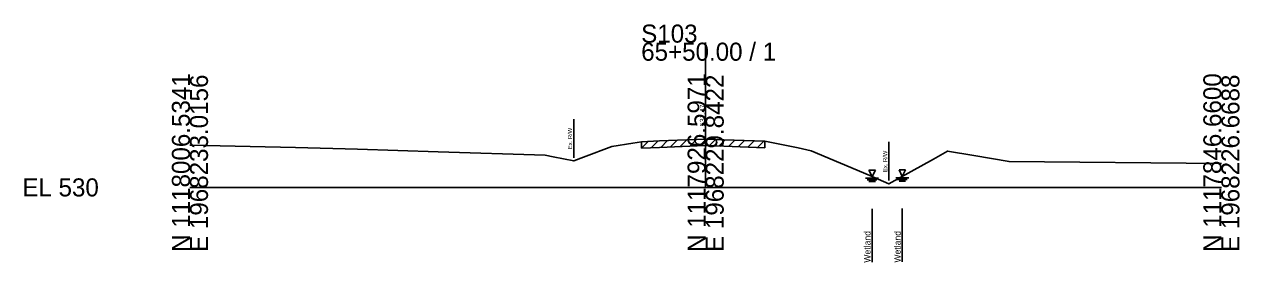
# Model space of a CAD drawing. Extents: x -26 to 163, y -10 to 24018.
# Drawn here: x -25.7 to 162.8, y 13488.3 to 13525.3 of the extents above; entities that cross this region are included whole.
import ezdxf

# ---------------------------------------------------------------- set-up
doc = ezdxf.new("R2010")
doc.units = 0
for name, color, linetype in [('RD_GPK_XS_Cell', 7, 'Continuous'), ('RD_XS_ExGround', 7, 'Continuous'), ('RD_XS_ExPaveRet', 7, 'Continuous'), ('RD_XS_ExRW', 7, 'Continuous'), ('RD_XS_EXWetland', 7, 'Continuous'), ('RD_XS_TX_Elev_EX', 7, 'Continuous')]:
    doc.layers.add(name, color=color, linetype=linetype)

msp = doc.modelspace()

# ---------------------------------------------------------------- linework, layer by layer
at = {"layer": 'RD_GPK_XS_Cell'}
for p, q in [((80, 13500), (80, 13522.43)), ((0, 13500), (80, 13500)), ((80, 13500), (160, 13500))]:
    msp.add_line(p, q, dxfattribs=at)
at = {"layer": 'RD_XS_ExGround'}
msp.add_lwpolyline([(0, 13506.55), (16.38, 13506.19), (26.01, 13505.93), (38.53, 13505.52), (55.09, 13504.98), (56.34, 13504.75), (59.53, 13504.1), (61.07, 13504.69), (65.47, 13506.33), (68.7, 13506.86), (70.04, 13507.08), (72.86, 13507.2), (79.89, 13507.48), (82.8, 13507.37), (89.2, 13507.15), (94.37, 13506.12), (96.38, 13505.69), (105.48, 13501.84), (108.41, 13500.55), (115.34, 13504.4), (117.53, 13505.64), (121.62, 13504.94), (127.08, 13504.01), (160, 13503.68)], dxfattribs=at)
at = {"layer": 'RD_XS_ExPaveRet'}
for p, q in [((70.04, 13506.08), (71.09, 13507.12)), ((70.04, 13506.08), (70.04, 13507.08)), ((71.54, 13506.14), (72.59, 13507.19)), ((73.04, 13506.21), (74.09, 13507.25)), ((74.54, 13506.27), (75.59, 13507.31)), ((76.04, 13506.32), (77.09, 13507.37)), ((77.54, 13506.38), (78.59, 13507.42)), ((79.04, 13506.44), (80.07, 13507.47)), ((80.54, 13506.45), (81.51, 13507.42)), ((82.04, 13506.4), (83.01, 13507.36)), ((83.54, 13506.34), (84.51, 13507.31)), ((85.04, 13506.29), (86.01, 13507.26)), ((86.54, 13506.24), (87.51, 13507.21)), ((88.04, 13506.19), (89.01, 13507.15)), ((89.2, 13507.15), (89.2, 13506.15)), ((70.04, 13506.08), (72.86, 13506.2)), ((72.86, 13506.2), (79.89, 13506.48)), ((79.89, 13506.48), (82.8, 13506.37)), ((82.8, 13506.37), (89.2, 13506.15))]:
    msp.add_line(p, q, dxfattribs=at)
at = {"layer": 'RD_XS_ExRW'}
for p, q in [((59.53, 13510.6), (59.53, 13504.6)), ((108.41, 13507.05), (108.41, 13501.05))]:
    msp.add_line(p, q, dxfattribs=at)
at = {"layer": 'RD_XS_EXWetland'}
for p, q in [((110, 13502.71), (110.5, 13501.71)), ((111, 13502.71), (110, 13502.71)), ((110.5, 13501.71), (111, 13502.71)), ((104.82, 13501.44), (106.82, 13501.44)), ((105.07, 13501.19), (106.57, 13501.19)), ((105.32, 13502.69), (105.82, 13501.69)), ((106.32, 13502.69), (105.32, 13502.69)), ((105.32, 13500.94), (106.32, 13500.94)), ((105.82, 13501.69), (106.32, 13502.69)), ((109.5, 13501.46), (111.5, 13501.46)), ((109.75, 13501.21), (111.25, 13501.21)), ((110, 13500.96), (111, 13500.96)), ((105.82, 13496.69), (105.82, 13488.44)), ((110.5, 13496.71), (110.5, 13488.46))]:
    msp.add_line(p, q, dxfattribs=at)

# ---------------------------------------------------------------- texts
at = {"layer": 'RD_GPK_XS_Cell'}
for s, p in [('S103', (70, 13522.43)), ('65+50.00 / 1', (70, 13519.63)), ('EL 530', (-26, 13498.6))]:
    msp.add_text(s, height=2.8, dxfattribs=at).set_placement(p)
for s, p in [('N 1118006.5341', (0, 13490)), ('E 1968233.0156', (2.8, 13490)), ('N 1117926.5971', (80, 13490)), ('E 1968229.8422', (82.8, 13490)), ('N 1117846.6600', (160, 13490)), ('E 1968226.6688', (162.8, 13490))]:
    msp.add_text(s, height=2.8, rotation=90, dxfattribs=at).set_placement(p)
at = {"layer": 'RD_XS_ExRW'}
for p in [(59.28, 13505.94), (108.16, 13502.39)]:
    msp.add_text('Ex. R/W ', height=0.65, rotation=90, dxfattribs=at).set_placement(p)
at = {"layer": 'RD_XS_EXWetland'}
for p in [(105.57, 13488.34), (110.25, 13488.35)]:
    msp.add_text('Wetland ', height=1, rotation=90, dxfattribs=at).set_placement(p)
at = {"layer": 'RD_XS_TX_Elev_EX'}
msp.add_text('537.47', height=0.8, rotation=90, dxfattribs=at).set_placement((79.9, 13509.47))

doc.saveas('drawing.dxf')
